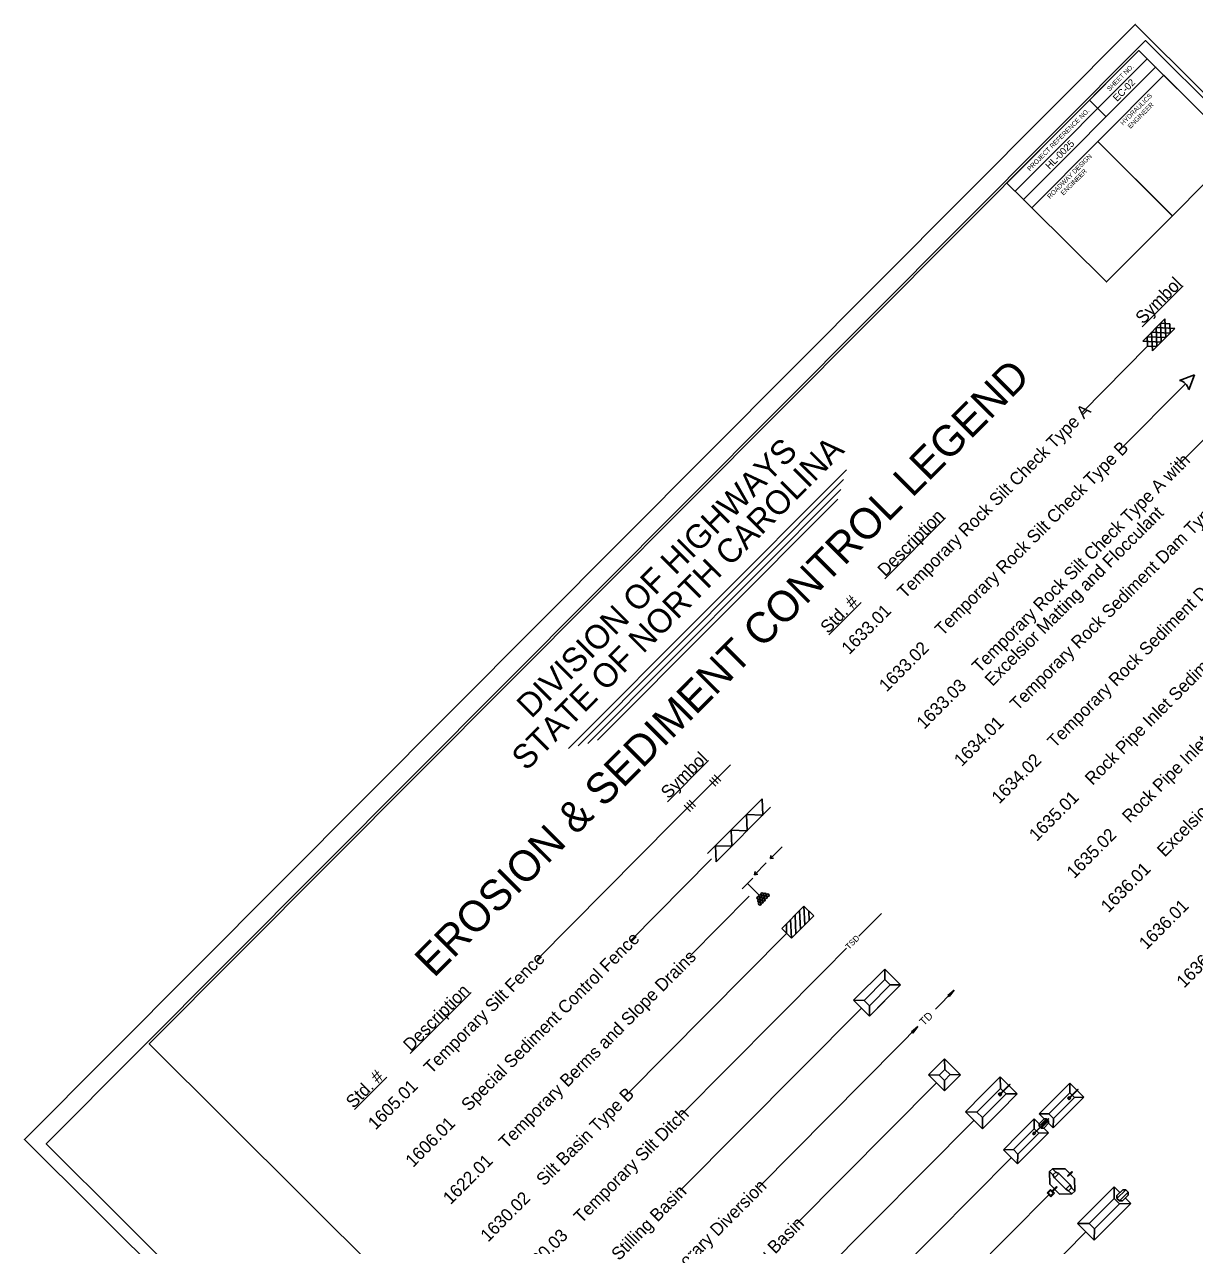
# Model space of a CAD drawing. Extents: x 1489771 to 1495672, y 500348 to 506262.
# Drawn here: x 1489771 to 1493531, y 502337 to 506262 of the extents above; entities that cross this region are included whole.
import ezdxf

# ---------------------------------------------------------------- set-up
doc = ezdxf.new("R2010")
doc.units = 0
for name, color, linetype in [('Old_Level_1', 7, 'Continuous'), ('Old_Level_12', 7, 'Continuous'), ('Sheet Plot Border Inside CELL', 7, 'Continuous')]:
    doc.layers.add(name, color=color, linetype=linetype)

msp = doc.modelspace()

# ---------------------------------------------------------------- linework, layer by layer
at = {"layer": 'Old_Level_1'}
for p, q in [((1492955, 505725.8), (1493379.2, 506151.7)), ((1492981.6, 505699.3), (1493405.8, 506125.2)), ((1493193.6, 506018.5), (1493246.8, 505965.5)), ((1493220.4, 505885.8), (1493459.8, 505647.4)), ((1492981.6, 505699.3), (1493008.3, 505672.8)), ((1493362.7, 505289.6), (1493494.6, 505422.2)), ((1493364.7, 505243.9), (1493436.2, 505315.8)), ((1493436.2, 505315.8), (1493439.1, 505256.3)), ((1493393, 505272.4), (1493396, 505212.9)), ((1493453.1, 505270.2), (1493393, 505272.4)), ((1493396, 505212.9), (1493467.5, 505284.7)), ((1493407.9, 505287.4), (1493410.4, 505227.3)), ((1493467.5, 505284.7), (1493407.9, 505287.4)), ((1493421.8, 505301.4), (1493424.2, 505241.2)), ((1493451.9, 505300.2), (1493421.8, 505301.4)), ((1493451.9, 505300.2), (1493453.1, 505270.2)), ((1493424.2, 505241.2), (1493364.7, 505243.9)), ((1493379.1, 505258.4), (1493380.3, 505228.3)), ((1493439.1, 505256.3), (1493379.1, 505258.4)), ((1493170.1, 505014.9), (1493380.3, 505228.3)), ((1493410.4, 505227.3), (1493380.3, 505228.3)), ((1493482.7, 505117.4), (1493531.1, 505135.8)), ((1493531.1, 505135.8), (1493512.7, 505087.5)), ((1493288.6, 504892.8), (1493501.8, 505107.3)), ((1493484, 504850.2), (1493621.4, 504988.2)), ((1491519.9, 503934.1), (1492412.9, 504830.8)), ((1491550.5, 503942.8), (1492403.5, 504799.3)), ((1491581.6, 503950.9), (1492394.6, 504767.3)), ((1491612.4, 503961), (1492384.6, 504736.4)), ((1492536, 504479.8), (1492731.3, 504675.9)), ((1492356.6, 504299.7), (1492460.4, 504404.1)), ((1491837.8, 503763.5), (1491969.7, 503896.1)), ((1491858.5, 503700.2), (1492040, 503882.4)), ((1491972.1, 503833.4), (1491992.5, 503813.1)), ((1491980.4, 503841.8), (1492000.8, 503821.5)), ((1491988.1, 503849.6), (1492008.7, 503829.2)), ((1491891.1, 503752.1), (1491911.5, 503731.7)), ((1491899.4, 503760.5), (1491919.8, 503740.1)), ((1491907.2, 503768.2), (1491927.6, 503747.9)), ((1491966.7, 503596.7), (1492141.7, 503772.2)), ((1491994.2, 503570.2), (1492168.6, 503745.4)), ((1492143.7, 503720.3), (1492141.7, 503772.2)), ((1491418.9, 503256.5), (1491858.5, 503700.2)), ((1492093.8, 503670.3), (1492091.8, 503722.2)), ((1492091.8, 503722.2), (1492143.7, 503720.3)), ((1492044, 503620.2), (1492042, 503672.1)), ((1492042, 503672.1), (1492093.8, 503670.3)), ((1491994.2, 503570.2), (1491992.2, 503622.1)), ((1491992.2, 503622.1), (1492044, 503620.2)), ((1491717.6, 503315.3), (1491979.1, 503580.1)), ((1492168.3, 503580.4), (1492170.2, 503590.7)), ((1492178.6, 503582.3), (1492168.3, 503580.4)), ((1492077.5, 503483.3), (1492111.4, 503517.2)), ((1492116.7, 503528.6), (1492119.2, 503539.4)), ((1492116.7, 503528.6), (1492119.2, 503539.4)), ((1492127.6, 503531), (1492116.7, 503528.6)), ((1492127.6, 503531), (1492116.7, 503528.6)), ((1492132, 503463.4), (1492095.3, 503499.9)), ((1491909.3, 503266.8), (1492099.6, 503460.1)), ((1492204.5, 503355.6), (1492276.1, 503427.5)), ((1492276.1, 503427.5), (1492279.2, 503367.9)), ((1492276.1, 503427.5), (1492307.4, 503396.4)), ((1492233.4, 503384.6), (1492235.8, 503324.5)), ((1492235.8, 503324.5), (1492307.4, 503396.4)), ((1492247.9, 503399), (1492250.2, 503339)), ((1492261.7, 503413), (1492264.7, 503353.4)), ((1492291.8, 503411.9), (1492293, 503381.9)), ((1492452.8, 503330.9), (1492525.2, 503403.6)), ((1492204.5, 503355.6), (1492235.8, 503324.5)), ((1492219.6, 503369.5), (1492220.2, 503340)), ((1491707.7, 502823.2), (1492220.2, 503340)), ((1492340.7, 503220), (1492413.1, 503292.7)), ((1491881.5, 502756.6), (1492340.7, 503220)), ((1492435.4, 503125.1), (1492535.5, 503225.6)), ((1492536.3, 503191.5), (1492535.5, 503225.6)), ((1492535.5, 503225.6), (1492586.6, 503174.7)), ((1491011.1, 502953.7), (1491206.4, 503149.8)), ((1492586.6, 503174.7), (1492486.5, 503074.2)), ((1492553.1, 503174.8), (1492586.6, 503174.7)), ((1492698.4, 503096.9), (1492758.8, 503157.6)), ((1492758.8, 503157.6), (1492738.2, 503140.6)), ((1492742.9, 503136.9), (1492758.8, 503157.6)), ((1492469.5, 503124.5), (1492435.4, 503125.1)), ((1492469.5, 503124.5), (1492435.4, 503125.1)), ((1492486.5, 503074.2), (1492435.4, 503125.1)), ((1492486.5, 503074.2), (1492435.4, 503125.1)), ((1492538.2, 503126.1), (1492486.5, 503074.2)), ((1492738.2, 503140.6), (1492742.9, 503136.9)), ((1491878.7, 502513.4), (1492461, 503099.7)), ((1492486.5, 503074.2), (1492486.3, 503107.7)), ((1492486.5, 503074.2), (1492486.3, 503107.7)), ((1492581.8, 502979.9), (1492642.3, 503040.7)), ((1492642.3, 503040.7), (1492621.7, 503023.5)), ((1492625.8, 503019.3), (1492642.3, 503040.7)), ((1492621.7, 503023.5), (1492625.8, 503019.3)), ((1490172.1, 502984.8), (1490172.1, 502984.8)), ((1492130.8, 502524.8), (1492581.8, 502979.9)), ((1492728.2, 502936.9), (1492676.5, 502885)), ((1492779.2, 502886), (1492728.2, 502936.9)), ((1492728.9, 502902.7), (1492728.2, 502936.9)), ((1490831.7, 502773.6), (1490935.6, 502878.1)), ((1492727.6, 502834.1), (1492676.5, 502885)), ((1492710.6, 502884.4), (1492676.5, 502885)), ((1492779.2, 502886), (1492727.6, 502834.1)), ((1492745.8, 502886.1), (1492779.2, 502886)), ((1492850.8, 502822.8), (1492906.5, 502878.6)), ((1492906.5, 502878.6), (1492961.4, 502823.9)), ((1492907.6, 502842.1), (1492906.5, 502878.6)), ((1492251.9, 502406.3), (1492702.1, 502859.6)), ((1492727.6, 502834.1), (1492727.4, 502867.6)), ((1492831.8, 502765.9), (1492907.7, 502841.9)), ((1492907.7, 502841.9), (1492925.5, 502824.2)), ((1492908.1, 502825.5), (1492937.6, 502855)), ((1492938.6, 502854), (1492909.1, 502824.5)), ((1492937.6, 502855), (1492938.6, 502854)), ((1493081.3, 502809.1), (1493130.7, 502858.6)), ((1493130.4, 502813.3), (1493156.5, 502839.4)), ((1493130.5, 502827.4), (1493130.7, 502858.6)), ((1493130.7, 502858.6), (1493175.8, 502813.7)), ((1493157.3, 502838.6), (1493131.2, 502812.5)), ((1493156.5, 502839.4), (1493157.3, 502838.6)), ((1492795.1, 502766.9), (1492850.8, 502822.8)), ((1492925.5, 502824.2), (1492849.7, 502748.2)), ((1492905.5, 502828.1), (1492900.2, 502822.8)), ((1492900.2, 502822.8), (1492906.4, 502816.6)), ((1492905.6, 502826.2), (1492902.1, 502822.7)), ((1492902.1, 502822.7), (1492906.3, 502818.5)), ((1492911.7, 502821.9), (1492905.5, 502828.1)), ((1492909.8, 502822), (1492905.6, 502826.2)), ((1492961.5, 502824), (1492905.8, 502768.1)), ((1492906.3, 502818.5), (1492909.8, 502822)), ((1492906.4, 502816.6), (1492911.7, 502821.9)), ((1492925.5, 502824.2), (1492961.4, 502823.9)), ((1493032.1, 502759.7), (1493081.3, 502809.1)), ((1493063.3, 502760), (1493130.6, 502827.3)), ((1493145.2, 502812.8), (1493078, 502745.4)), ((1493128.2, 502815.5), (1493123.5, 502810.7)), ((1493123.5, 502810.7), (1493128.6, 502805.6)), ((1493128.2, 502813.8), (1493125.2, 502810.7)), ((1493125.2, 502810.7), (1493128.6, 502807.3)), ((1493175.9, 502813.7), (1493126.6, 502764.2)), ((1493133.3, 502810.4), (1493128.2, 502815.5)), ((1493131.7, 502810.4), (1493128.2, 502813.8)), ((1493128.6, 502805.6), (1493133.3, 502810.4)), ((1493128.6, 502807.3), (1493131.7, 502810.4)), ((1493130.6, 502827.3), (1493145.2, 502812.8)), ((1493145.2, 502812.8), (1493175.8, 502813.7)), ((1492831.8, 502765.9), (1492795.1, 502766.9)), ((1492850.1, 502712.1), (1492795.1, 502766.9)), ((1492849.7, 502748.2), (1492831.8, 502765.9)), ((1492905.8, 502768.1), (1492850.1, 502712.1)), ((1493063.3, 502760), (1493032.1, 502759.7)), ((1493047.6, 502744.1), (1493032.1, 502759.7)), ((1493078, 502745.4), (1493063.3, 502760)), ((1493126.6, 502764.2), (1493077.2, 502714.7)), ((1492277.2, 502190.4), (1492822.6, 502739.5)), ((1492850.1, 502712.1), (1492849.8, 502748.2)), ((1492967, 502694.3), (1493016.3, 502743.8)), ((1493016.1, 502712.6), (1493016.3, 502743.8)), ((1493031.9, 502728.3), (1493016.3, 502743.8)), ((1493017.6, 502699.8), (1493062.4, 502744.7)), ((1493063.3, 502743.9), (1493018.4, 502698.9)), ((1493031.9, 502720.2), (1493055.6, 502744.2)), ((1493031.9, 502728.3), (1493047.6, 502744.1)), ((1493031.9, 502728.3), (1493031.9, 502720.2)), ((1493031.9, 502720.2), (1493038.5, 502713.7)), ((1493062.2, 502737.6), (1493038.5, 502713.7)), ((1493046.5, 502713.7), (1493062.2, 502729.6)), ((1493047.6, 502744.1), (1493055.6, 502744.2)), ((1493055.6, 502744.2), (1493062.2, 502737.6)), ((1493062.2, 502729.6), (1493062.2, 502737.6)), ((1493077.2, 502714.7), (1493062.2, 502729.6)), ((1493062.4, 502744.7), (1493063.3, 502743.9)), ((1493077.2, 502714.7), (1493078.1, 502745.4)), ((1492917.7, 502644.8), (1492967, 502694.3)), ((1492949, 502645.2), (1493016.2, 502712.4)), ((1493030.8, 502697.9), (1492963.6, 502630.6)), ((1493015.5, 502701.9), (1493010.7, 502697.1)), ((1493010.7, 502697.1), (1493015.8, 502692.1)), ((1493061.5, 502698.9), (1493012.2, 502649.4)), ((1493015.5, 502700.2), (1493012.4, 502697.1)), ((1493012.4, 502697.1), (1493015.8, 502693.7)), ((1493020.6, 502696.8), (1493015.5, 502701.9)), ((1493018.9, 502696.8), (1493015.5, 502700.2)), ((1493015.8, 502692.1), (1493020.6, 502696.8)), ((1493015.8, 502693.7), (1493018.9, 502696.8)), ((1493016.2, 502712.4), (1493030.8, 502697.9)), ((1493030.8, 502697.9), (1493061.5, 502698.8)), ((1493046.5, 502713.7), (1493038.5, 502713.7)), ((1493046.5, 502713.7), (1493061.5, 502698.8)), ((1492949, 502645.2), (1492917.7, 502644.8)), ((1492962.8, 502599.8), (1492917.7, 502644.8)), ((1492963.6, 502630.6), (1492949, 502645.2)), ((1493012.2, 502649.4), (1492962.8, 502599.8)), ((1492514, 502187.4), (1492943.2, 502619.5)), ((1492962.8, 502599.8), (1492963.7, 502630.6)), ((1493065.3, 502574.2), (1493074.4, 502583.4)), ((1493076, 502563.5), (1493065.3, 502574.2)), ((1493065.3, 502574.2), (1493065.7, 502533.9)), ((1493074.4, 502583.4), (1493115.1, 502583.5)), ((1493085.1, 502572.7), (1493074.4, 502583.4)), ((1493076, 502563.5), (1493085.1, 502572.7)), ((1493081, 502554.3), (1493076, 502563.5)), ((1493081, 502554.3), (1493094.8, 502568.1)), ((1493094.8, 502568.1), (1493085.1, 502572.7)), ((1493094.8, 502568.1), (1493131.1, 502532)), ((1493115.1, 502583.5), (1493130.2, 502568.5)), ((1493123, 502561.3), (1493125, 502559.4)), ((1493136.8, 502575.1), (1493123.1, 502561.3)), ((1493138.7, 502573.1), (1493125, 502559.4)), ((1493132.1, 502566.5), (1493146, 502552.7)), ((1493136.8, 502575.1), (1493138.7, 502573.1)), ((1493065.7, 502533.9), (1493080.7, 502519)), ((1493073.8, 502512.1), (1493087.8, 502526.1)), ((1493075.8, 502510.1), (1493089.8, 502524.1)), ((1493081, 502554.3), (1493117.3, 502518.2)), ((1493087.8, 502526.1), (1493089.8, 502524.1)), ((1493131.1, 502532), (1493117.3, 502518.1)), ((1493135.7, 502522.2), (1493126.6, 502513.1)), ((1493131.1, 502532), (1493135.7, 502522.2)), ((1493146.4, 502511.5), (1493135.7, 502522.2)), ((1493146, 502552.7), (1493146.4, 502511.5)), ((1493214, 502466.4), (1493272.7, 502525.4)), ((1493272.5, 502488.2), (1493272.7, 502525.4)), ((1493272.7, 502525.4), (1493291.3, 502506.8)), ((1492722.3, 502156.2), (1493063.4, 502499.7)), ((1493068.7, 502517.2), (1493057.3, 502505.8)), ((1493057.3, 502505.8), (1493069.6, 502493.5)), ((1493068.7, 502513.2), (1493061.3, 502505.8)), ((1493061.3, 502505.8), (1493069.6, 502497.6)), ((1493081, 502505), (1493068.7, 502517.2)), ((1493077, 502505), (1493068.7, 502513.2)), ((1493069.6, 502493.5), (1493081, 502505)), ((1493069.6, 502497.6), (1493077, 502505)), ((1493082.7, 502517), (1493097.5, 502502.3)), ((1493097.5, 502502.3), (1493137.3, 502502.4)), ((1493117.3, 502518.2), (1493126.6, 502513.1)), ((1493137.3, 502502.4), (1493126.6, 502513.1)), ((1493137.3, 502502.4), (1493146.4, 502511.5)), ((1493192.5, 502407.9), (1493272.6, 502488)), ((1493272.6, 502488), (1493290, 502470.7)), ((1493282, 502497.4), (1493300.7, 502516.3)), ((1493282, 502487.8), (1493310.2, 502516.3)), ((1493282, 502497.4), (1493282, 502487.8)), ((1493282, 502487.8), (1493289.8, 502480)), ((1493318.1, 502508.5), (1493289.8, 502480)), ((1493299.4, 502480.1), (1493318.1, 502498.9)), ((1493300.7, 502516.3), (1493310.2, 502516.3)), ((1493326.5, 502471.8), (1493308.7, 502489.6)), ((1493310.2, 502516.3), (1493318.1, 502508.5)), ((1493318.1, 502498.9), (1493318.1, 502508.5)), ((1493155.2, 502407.5), (1493214, 502466.4)), ((1493209, 502353.8), (1493326.5, 502471.8)), ((1493290, 502470.7), (1493210, 502390.5)), ((1493299.4, 502480.1), (1493289.8, 502480)), ((1493290, 502470.7), (1493326.5, 502471.8)), ((1493192.5, 502407.9), (1493155.2, 502407.5)), ((1493209, 502353.8), (1493155.2, 502407.5)), ((1493210, 502390.5), (1493192.5, 502407.9)), ((1492658.6, 501853.6), (1493182.1, 502380.6)), ((1493209, 502353.8), (1493210.1, 502390.5))]:
    msp.add_line(p, q, dxfattribs=at)
for points in [[(1493352.5, 506178.3), (1490172.1, 502984.8), (1492407.6, 500758.5), (1495587.9, 503952.1)], [(1492928.3, 505752.4), (1493352.5, 506178.3), (1493405.8, 506125.2), (1492981.6, 505699.3)], [(1493220.4, 505885.8), (1493432.4, 506098.7), (1493671.9, 505860.2), (1493459.9, 505647.3)], [(1493008.3, 505672.8), (1493220.4, 505885.8), (1493459.9, 505647.3), (1493247.8, 505434.3)], [(1492486.3, 503107.7), (1492469.5, 503124.5), (1492536.3, 503191.5), (1492553.1, 503174.8)], [(1492727.4, 502867.6), (1492710.6, 502884.4), (1492728.9, 502902.7), (1492745.8, 502886.1)]]:
    msp.add_lwpolyline(points, close=True, dxfattribs=at)
for points in [[(1492168.3, 503580.4), (1492206, 503618.3)], [(1492116.7, 503528.6), (1492154.4, 503566.5)], [(1492116.7, 503528.6), (1492154.4, 503566.5)]]:
    msp.add_lwpolyline(points, dxfattribs=at)
msp.add_ellipse((1493478.6, 505083.9), major_axis=(25.2, -25.1), ratio=0.927398, start_param=0.944994, end_param=2.196599, dxfattribs=at)
for centre in [(1492135.2, 503460.4), (1492141.6, 503466.7), (1492150.8, 503465.1), (1492159.9, 503462.6), (1492129.4, 503454), (1492131.7, 503444.7), (1492133.9, 503435.4), (1492138.2, 503451.3), (1492140.4, 503442), (1492144.3, 503457.4), (1492146.8, 503448.4), (1492153.5, 503456.3)]:
    msp.add_ellipse(centre, major_axis=(-3.12, 3.11), ratio=0.927398, dxfattribs=at)
at = {"layer": 'Old_Level_12'}
msp.add_lwpolyline([(1492102.5, 500356.3), (1495671.9, 503940.6), (1493340.6, 506262.2), (1489771.2, 502678)], close=True, dxfattribs=at)
at = {"layer": 'Sheet Plot Border Inside CELL'}
msp.add_lwpolyline([(1492087.5, 500426.4), (1495619.8, 503973.4), (1493373.6, 506210.2), (1489841.3, 502663.3)], close=True, dxfattribs=at)

# ---------------------------------------------------------------- texts
at = {"layer": 'Old_Level_1'}
for s, height, rotation, p in [('SHEET NO.', 15.02, 45.1186, (1493258.6, 506046.6)), ('EC-02', 22.54, 45.1186, (1493282.3, 506012.9)), ('HYDRAULICS', 15.02, 45.1186, (1493301.8, 505936.4)), ('PROJECT REFERENCE NO.', 15.024, 45.1186, (1493002.2, 505789.6)), ('ENGINEER', 15.02, 45.1186, (1493325.1, 505926)), ('HL-0025', 22.54, 45.1186, (1493065.6, 505795)), ('ROADWAY DESIGN', 15.024, 45.1186, (1493066.9, 505700.6)), ('ENGINEER', 15.02, 45.1186, (1493110.2, 505711.9)), ('Symbol', 40.76, 45.1186, (1493365.8, 505296.4)), ('EROSION & SEDIMENT CONTROL LEGEND', 99.051, 45.1186, (1491086.8, 503194.8)), ('Temporary Rock Silt Check Type A', 40.761, 45.1186, (1492600.7, 504414.3)), ('STATE OF NORTH CAROLINA', 77.039, 45.1186, (1491383.9, 503859.9)), (' DIVISION OF HIGHWAYS', 77.039, 44.8885, (1491379.7, 504008.1)), ('Temporary Rock Silt Check Type B', 40.761, 45.1186, (1492721.3, 504294.3)), ('Temporary Rock Silt Check Type A with', 40.761, 45.1186, (1492840.7, 504175.3)), ('Temporary Rock Sediment Dam Type A', 40.777, 45.1186, (1492962.4, 504054.1)), ('Description', 40.761, 45.1186, (1492537.5, 504485)), ('Excelsior Matting and Flocculant', 40.761, 45.1186, (1492881.6, 504132.3)), ('Temporary Rock Sediment Dam Type B', 40.761, 45.1186, (1493082.6, 503933.9)), ('Rock Pipe Inlet Sediment Trap Type A', 40.704, 45.1186, (1493203.4, 503814.1)), ('Std. #', 40.76, 45.1186, (1492353.5, 504301.7)), ('1633.01', 40.71, 45.1186, (1492421.3, 504234.2)), ('Rock Pipe Inlet Sediment Trap Type B', 40.704, 45.1186, (1493322.9, 503693)), ('1633.02', 40.71, 45.1186, (1492541.8, 504114.2)), ('1633.03', 40.71, 45.1186, (1492662.4, 503994.1)), ('1634.01', 40.71, 45.1186, (1492782.9, 503874.1)), ('Excelsior Wattle Check', 40.761, 45.1186, (1493435.1, 503583.3)), ('Symbol', 40.76, 45.1186, (1491840.9, 503770.3)), ('1634.02', 40.71, 45.1186, (1492903.5, 503754)), ('1635.01', 40.71, 45.1186, (1493024, 503634)), ('1635.02', 40.71, 45.1186, (1493144.6, 503513.9)), ('1636.01', 40.71, 45.1186, (1493254.6, 503404.4)), ('1636.01', 40.71, 45.1186, (1493377.1, 503285.6)), ('Special Sediment Control Fence', 40.761, 45.1186, (1491199.4, 502766.1)), ('TSD', 19.05, 45.1186, (1492420.7, 503287.2)), ('1636.01', 40.71, 45.1186, (1493497.8, 503162.2)), ('Temporary Silt Fence', 40.761, 45.1186, (1491078.9, 502886.2)), ('Temporary Berms and Slope Drains ', 40.704, 45.1186, (1491320, 502646.1)), ('Description', 40.761, 45.1186, (1491012.6, 502958.9)), ('TD', 24.72, 45.1186, (1492661.8, 503041.7)), ('Std. #', 40.76, 45.1186, (1490828.7, 502775.6)), ('1605.01', 40.71, 45.1186, (1490899.5, 502706.1)), ('Silt Basin Type B', 40.761, 45.1186, (1491440.5, 502526)), ('Temporary Silt Ditch', 40.761, 45.1186, (1491561.1, 502406)), ('1606.01', 40.71, 45.1186, (1491020, 502586.1)), ('1622.01', 40.71, 45.1186, (1491140.6, 502466)), ('Stilling Basin', 40.761, 45.1186, (1491681.6, 502285.9)), ('Temporary Diversion', 40.777, 45.1186, (1491802.2, 502165.9)), ('1630.02', 40.71, 45.1186, (1491261.1, 502346)), ('Special Stilling Basin', 40.761, 45.1186, (1491922.7, 502045.8)), ('1630.03', 40.71, 45.1186, (1491381.7, 502225.9))]:
    msp.add_text(s, height=height, rotation=rotation, dxfattribs=at).set_placement(p)

doc.saveas('drawing.dxf')
